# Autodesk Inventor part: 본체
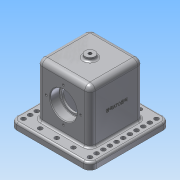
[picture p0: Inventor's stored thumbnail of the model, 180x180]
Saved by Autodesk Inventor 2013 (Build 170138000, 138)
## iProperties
Created: 2018-11
Part Number: 본체
Material: 알루미늄 6061
Document SubType Name: Modeling
Designer: kg
Density: 2.71 g/cm^3
Mass: 1020.7 g
Surface Area: 776.599 cm^2
Volume: 376.644 cm^3
Author: kg
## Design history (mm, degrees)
sketch "스케치1"
  geometry: L1 (-40, -40)-(40, -40); L2 (40, -40)-(40, 40); L3 (40, 40)-(-40, 40); L4 (-40, 40)-(-40, -40); 3 further points
  constraints: 8 end point, 2 midpoint, 2 parallel, 2 perpendicular, 1 horizontal, 1 horizontal alignment, 1 vertical alignment
  dimensions: "d0" = 80 distance of L2.end L3.end
extrude "돌출1" new body sketch "스케치1" distance "d2" = 80; taper "d3" = 0 deg
node "작업 평면1"
sketch "스케치2"
  geometry: L1 (-20, -20)-(100, -20); L2 (100, -20)-(100, 100); L3 (100, 100)-(-20, 100); L4 (-20, 100)-(-20, -20); L5 (0, 80)-(80, 80) reference; L6 (0, 0)-(80, 0) reference; L7 (80, 0)-(80, 80) reference; L8 (0, 80)-(80, 80) reference; L9 (0, 0)-(0, 80) reference; 4 further points
  constraints: 8 end point, 3 midpoint, 2 parallel, 2 perpendicular, 1 horizontal, 1 horizontal alignment, 1 vertical alignment
  dimensions: "d5" = 120 distance of L2.end L3.end
extrude "돌출2" join sketch "스케치2" stored distance "d7" = 10; taper "d8" = 0 deg
node "작업 평면2"
sketch "스케치3"
  geometry: L1 (80, 0)-(0, 0) reference; L2 (80, 0)-(80, 80) reference; C1 r 7.5 at (40, 40); 3 further points
  constraints: 2 midpoint, 1 centre point, 1 horizontal alignment, 1 vertical alignment
  dimensions: "d10" = 15 diameter of C1
extrude "돌출3" join sketch "스케치3" stored distance "d11" = 80; taper "d12" = 0 deg
sketch "스케치5"
  geometry: L1 (120, -120)-(120, 0) reference; L2 (120, 0)-(0, 0) reference; L3 (0, 0)-(0, -120) reference; L4 (0, -120)-(120, -120) reference; L5 (100, -20)-(100, -100) reference; L6 (20, -100)-(100, -100) reference; L7 (20, -20)-(20, -100) reference; L8 (20, -20)-(100, -20) reference; 1 further point
sketch "스케치7"
  geometry: L1 (100, -20)-(100, 100) reference; L2 (17, 10)-(63, 10); L3 (63, 10)-(63, 70); L4 (63, 70)-(17, 70); L5 (17, 70)-(17, 10); 4 further points
  constraints: 8 end point, 3 midpoint, 2 parallel, 1 horizontal, 1 horizontal alignment, 1 perpendicular, 1 vertical alignment
  dimensions: "d20" = 46 distance of L2.start L2.end; "d22" = 60 distance of L2.end L3.end
extrude "돌출5" cut sketch "스케치7" distance "d23" = 80; taper "d24" = 0 deg
sketch "스케치8"
  geometry: L1 (80, 0)-(80, -80) reference; L2 (0, 0)-(80, 0) reference; L3 (100, -90)-(-20, -90) reference; C1 r 16.5 at (40, -42); 3 further points
  constraints: 2 midpoint, 1 centre point, 1 vertical alignment
  dimensions: "d25" = 33 diameter of C1; "d91" = 48 distance from line of C1.centre L3
extrude "돌출6" cut sketch "스케치8" distance "d26" = 80; taper "d27" = 0 deg
sketch "스케치9"
  geometry: C1 r 16.5 at (40, -42) reference; C2 r 20 at (40, -42); 1 further point
  constraints: 1 centre point, 1 coincident
  dimensions: "d28" = 40 diameter of C2
extrude "돌출7" cut sketch "스케치9" distance "d29" = 14; taper "d30" = 0 deg
node "작업 평면3"
sketch "스케치10"
  geometry: C1 r 7.5 at (0, 0) reference; 1 further point
sketch "스케치11"
  geometry: C1 r 7.5 at (0, 0) reference; 2 further points
  constraints: 1 coincident
hole "구멍1" sketch "스케치11" at (0, 0) diameter "d31" = 4.917; stored, may be unused: countersink angle "d35" = 90 deg, drill point angle "d37" = 118 deg; dims "d32" = 30, "d33" = 4, "d34" = 2, "d36" = 8
sketch "스케치12"
  geometry: L1 (120, -120)-(120, 0) reference; L2 (0, 0)-(0, -120) reference; L3 (0, -60)-(120, -60); C1 r 3.3 at (10, -10); C2 r 3.3 at (20, -10); C3 r 3.3 at (30, -10); C4 r 3.3 at (40, -10); C5 r 3.3 at (50, -10); C6 r 3.3 at (60, -10); 2 further points
  constraints: 6 centre point, 5 equal radius, 5 horizontal alignment, 3 midpoint, 2 end point, 1 vertical alignment
  dimensions: "d38" = 6.6 diameter of C1; "d40" = 100 diameter of C1.centre L3; "d41" = 10 distance of C2.centre C1.centre; "d42" = 10 distance of C3.centre C2.centre; "d43" = 10 distance of C4.centre C3.centre; "d44" = 10 distance of C5.centre C4.centre; "d45" = 10 distance of C6.centre C5.centre
extrude "돌출8" cut sketch "스케치12" distance "d46" = 14; taper "d47" = 0 deg
sketch "스케치13"
  geometry: L1 (0, -120)-(120, -120) reference; C1 r 3.3 at (10, -10) reference; C2 r 2.458 at (60, -60) reference; C3 r 3.3 at (10, -110); C4 r 3.3 at (10, -85); C5 r 3.3 at (10, -60); C6 r 3.3 at (10, -35); 1 further point
  constraints: 4 centre point, 4 vertical alignment, 3 equal radius
  dimensions: "d56" = 6.6 diameter of C3; "d58" = 25 distance of C1.centre C6.centre; "d59" = 25 distance of C6.centre C5.centre; "d60" = 25 distance of C4.centre C5.centre; "d61" = 10 distance from line of L1 C3.centre
extrude "돌출9" cut sketch "스케치13" distance "d62" = 14; taper "d63" = 0 deg
node "작업 평면4"
sketch "스케치14"
  geometry: C1 r 20 at (40, -42) reference; 5 further points
  constraints: 2 horizontal alignment, 2 vertical alignment
  dimensions: "d64" = 52 distance of point (40, -68) point (40, -16); "d66" = 52 distance of point (66, -42) point (14, -42); "d67" = 26 distance of C1.centre point (40, -16); "d68" = 26 distance of C1.centre point (66, -42)
hole "구멍2" sketch "스케치14" at (40, -16), (66, -42), (40, -68), (14, -42) diameter "d69" = 3.242; stored, may be unused: countersink angle "d73" = 90 deg, drill point angle "d75" = 118 deg; dims "d70" = 8, "d71" = 4, "d72" = 2, "d74" = 10
node "작업 평면5"
sketch "스케치15"
  geometry: L1 (60, -50)-(-60, -50) reference; 2 further points
  constraints: 1 vertical alignment, 1 other
  dimensions: "d77" = 48 distance from line of L1 point (0, -2)
feature "엠보싱1" sketch "스케치15" dims "d5" = 120, "d78" = 0.5, "d79" = 0
fillet "모깎기1" dims "d80" = 0.6
fillet "모깎기2" dims "d81" = 0.6
chamfer "모따기1" distance "d82" = 1; stored, may be unused: second distance "d83" = 2, angle "d84" = 45 deg
fillet "모깎기3" dims "d85" = 3
fillet "모깎기4" dims "d86" = 8
fillet "모깎기5" dims "d87" = 3
fillet "모깎기6" dims "d88" = 3
fillet "모깎기7" dims "d89" = 10
fillet "모깎기8" dims "d90" = 3
node "솔리드1"
mirror "대칭1"
mirror "대칭2"
mirror "대칭3"
mirror "대칭4"
mirror "대칭5"
node "투영된 루프1"
other parameters: "d9" = -95, "d76" = 5
